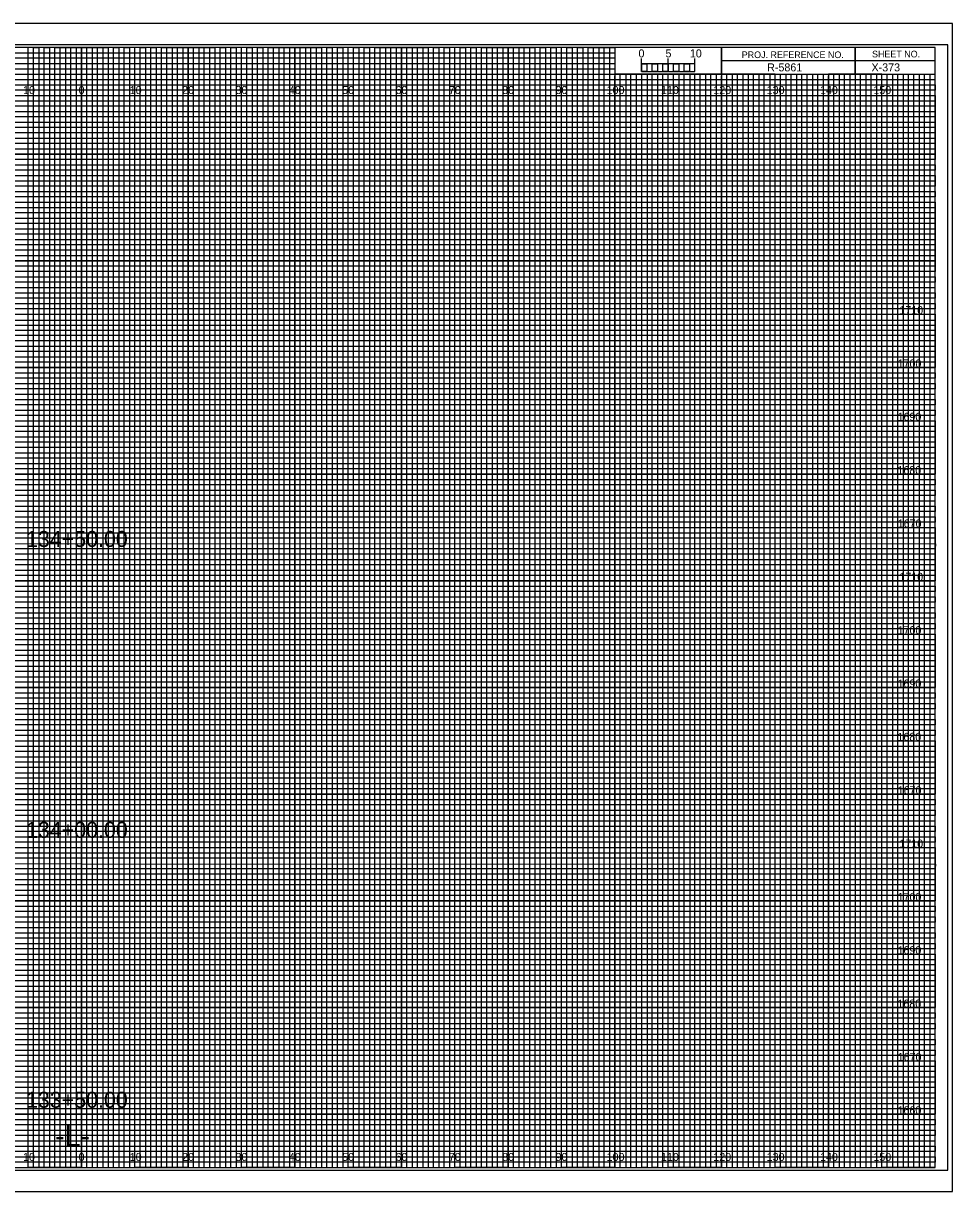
# Model space of a CAD drawing. Extents: x -13 to 323, y -5 to 2414.
# Drawn here: x 149.1 to 323.3, y 1975.5 to 2194.5 of the extents above; entities that cross this region are included whole.
import ezdxf

# ---------------------------------------------------------------- set-up
doc = ezdxf.new("R2010")
doc.units = 0
for name, color, linetype in [('Prop XS Alignment Label', 7, 'Continuous'), ('Prop XS Bar Scale Labels', 7, 'Continuous'), ('Prop XS Elevation Labels', 7, 'Continuous'), ('Prop XS Offset Labels', 7, 'Continuous'), ('Prop XS Project Number', 7, 'Continuous'), ('Prop XS Sheet Number', 7, 'Continuous'), ('Prop XS Station Labels', 7, 'Continuous'), ('Sheet Cross Section CELL', 7, 'Continuous'), ('Sheet Cross Section Grid Major CELL', 7, 'Continuous'), ('Sheet Cross Section Grid Middle CELL', 7, 'Continuous'), ('Sheet Cross Section Grid Minor 1 CELL', 7, 'Continuous'), ('Sheet Cross Section Grid Minor 2 CELL', 7, 'Continuous'), ('Sheet Cross Section Scale CELL', 7, 'Continuous'), ('Sheet Cutting Line CELL', 7, 'Continuous'), ('Sheet DOT Grid CELL', 7, 'Continuous'), ('Sheet Plot Border Inside CELL', 7, 'Continuous'), ('Sheet Plot Border Outside CELL', 7, 'Continuous')]:
    doc.layers.add(name, color=color, linetype=linetype)

msp = doc.modelspace()

# ---------------------------------------------------------------- linework, layer by layer
at = {"layer": 'Sheet Cross Section CELL'}
for p, q in [((305, 2190), (305, 2185)), ((305, 2185), (305, 2190)), ((280, 2187.5), (280, 2185)), ((320, 2187.49), (280, 2187.49)), ((280, 2185), (320, 2185))]:
    msp.add_line(p, q, dxfattribs=at)
for points in [[(320, 2190), (0, 2190), (0, 1980), (320, 1980)], [(280, 2190), (260, 2190), (260, 2185.03), (280, 2185.03)], [(320, 2190), (280, 2190), (280, 2185), (320, 2185)]]:
    msp.add_lwpolyline(points, close=True, dxfattribs=at)
at = {"layer": 'Sheet Cross Section Grid Major CELL'}
for p, q in [((150, 2190), (140, 2190)), ((150, 1980), (150, 2190)), ((170, 2190), (160, 2190)), ((160, 2190), (160, 1980)), ((170, 1980), (170, 2190)), ((190, 2190), (180, 2190)), ((180, 2190), (180, 1980)), ((190, 1980), (190, 2190)), ((210, 2190), (200, 2190)), ((200, 2190), (200, 1980)), ((210, 1980), (210, 2190)), ((230, 2190), (220, 2190)), ((220, 2190), (220, 1980)), ((230, 1980), (230, 2190)), ((250, 2190), (240, 2190)), ((240, 2190), (240, 1980)), ((250, 1980), (250, 2190)), ((260, 2190), (260, 1980)), ((270, 1980), (270, 2185)), ((290, 2185), (280, 2185)), ((280, 2185), (280, 1980)), ((290, 1980), (290, 2185)), ((310, 2185), (300, 2185)), ((300, 2185), (300, 1980)), ((310, 1980), (310, 2185)), ((160, 1980), (150, 1980)), ((180, 1980), (170, 1980)), ((200, 1980), (190, 1980)), ((220, 1980), (210, 1980)), ((240, 1980), (230, 1980)), ((260, 1980), (250, 1980)), ((280, 1980), (270, 1980)), ((300, 1980), (290, 1980)), ((320, 1980), (310, 1980)), ((320, 1980), (320, 1980))]:
    msp.add_line(p, q, dxfattribs=at)
for points in [[(0, 2180), (320, 2180), (320, 2170), (0, 2170)], [(0, 2160), (320, 2160), (320, 2150), (0, 2150)], [(0, 2140), (320, 2140), (320, 2130), (0, 2130)], [(0, 2120), (320, 2120), (320, 2110), (0, 2110)], [(0, 2100), (320, 2100), (320, 2090), (0, 2090)], [(0, 2080), (320, 2080), (320, 2070), (0, 2070)], [(0, 2060), (320, 2060), (320, 2050), (0, 2050)], [(0, 2040), (320, 2040), (320, 2030), (0, 2030)], [(0, 2020), (320, 2020), (320, 2010), (0, 2010)], [(0, 2000), (320, 2000), (320, 1990), (0, 1990)]]:
    msp.add_lwpolyline(points, dxfattribs=at)
at = {"layer": 'Sheet Cross Section Grid Middle CELL'}
for points in [[(145, 1980), (155, 1980), (155, 2190), (165, 2190), (165, 1980), (175, 1980), (175, 2190), (185, 2190), (185, 1980), (195, 1980), (195, 2190), (205, 2190), (205, 1980), (215, 1980), (215, 2190), (225, 2190), (225, 1980), (235, 1980), (235, 2190), (245, 2190), (245, 1980), (255, 1980), (255, 2190), (259.93, 2190), (260, 2190), (260, 2185), (264.99, 2185), (264.99, 1980), (275, 1980), (275, 2185), (285, 2185), (285, 1980), (295, 1980), (295, 2185), (305, 2185), (305, 1980), (315, 1980), (315, 2185)], [(0, 2185), (275, 2185)], [(0, 2165), (320, 2165), (320, 2175), (0, 2175)], [(0, 2145), (320, 2145), (320, 2155), (0, 2155)], [(0, 2125), (320, 2125), (320, 2135), (0, 2135)], [(0, 2105), (320, 2105), (320, 2115), (0, 2115)], [(0, 2085), (320, 2085), (320, 2095), (0, 2095)], [(0, 2065), (320, 2065), (320, 2075), (0, 2075)], [(0, 2045), (320, 2045), (320, 2055), (0, 2055)], [(0, 2025), (320, 2025), (320, 2035), (0, 2035)], [(0, 2005), (320, 2005), (320, 2015), (0, 2015)], [(0, 1985), (320, 1985), (320, 1995), (0, 1995)]]:
    msp.add_lwpolyline(points, dxfattribs=at)
at = {"layer": 'Sheet Cross Section Grid Minor 1 CELL'}
for p, q in [((0, 2189), (260, 2189)), ((260, 2187.98), (0, 2187.98)), ((260, 2189), (260, 2187.98)), ((0, 2187), (260, 2187)), ((260, 2185.89), (0, 2185.89)), ((260, 2187), (260, 2185.89)), ((0, 2184), (320, 2184))]:
    msp.add_line(p, q, dxfattribs=at)
for points in [[(0, 2183), (270, 2183), (320, 2183), (320, 2182), (0, 2182)], [(0, 2181), (320, 2181), (320, 2179), (0, 2179)], [(0, 2178), (320, 2178), (320, 2177), (0, 2176.98)], [(0, 2176), (320, 2176), (320, 2174), (0, 2174)], [(0, 2173), (320, 2173), (320, 2172), (0, 2172)], [(0, 2171), (320, 2171), (320, 2169), (0, 2169)], [(0, 2168), (320, 2168), (320, 2167), (0, 2167)], [(0, 2166), (320, 2166), (320, 2164), (0, 2164)], [(0, 2163), (320, 2163), (320, 2162), (0, 2162)], [(0, 2161), (320, 2161), (320, 2159), (0, 2159)], [(0, 2158), (320, 2158), (320, 2157), (0, 2157)], [(0, 2156), (320, 2156), (320, 2153.95), (320, 2153), (320, 2152), (0, 2152)], [(0, 2154), (320, 2154), (320, 2153), (0, 2153)], [(0, 2151), (320, 2151), (320, 2149), (0, 2149.03)], [(0, 2149.03), (320, 2149), (320, 2148), (0, 2148)], [(0, 2147), (320, 2147), (320, 2146), (0, 2146)], [(0, 2144), (320, 2144), (320, 2143), (0, 2143)], [(0, 2142), (320, 2142), (320, 2141), (0, 2141)], [(-0.07, 2138.89), (320, 2138.89), (320, 2137.88), (-0.07, 2137.88)], [(0, 2137), (320, 2137), (320, 2136), (0, 2136)], [(0, 2134), (320, 2134), (320, 2133), (0, 2133)], [(0, 2132), (320, 2132), (320, 2131), (0, 2131)], [(0, 2129), (320, 2129), (320, 2128), (0, 2128)], [(0, 2127), (320, 2127), (320, 2126), (0, 2126)], [(0, 2124), (320, 2124), (320, 2123), (0, 2123)], [(0, 2122), (320, 2122), (320, 2121), (0, 2121)], [(0, 2119), (320, 2119), (319.99, 2117.98), (0, 2118)], [(0, 2117), (320, 2117), (320, 2116), (0, 2116)], [(0, 2114), (320, 2114), (320, 2113), (0, 2113)], [(0, 2112), (320, 2112), (320, 2111), (0, 2111)], [(0, 2109), (320, 2109), (320, 2108), (0, 2108)], [(0, 2107), (320, 2107), (320, 2106), (0, 2106)], [(0, 2104), (320, 2104), (320, 2103), (0, 2103)], [(0, 2102), (320, 2102), (320, 2101), (0, 2101)], [(0, 2099), (320, 2099), (320, 2098), (0, 2098)], [(0, 2096.99), (320.07, 2096.91), (320, 2096), (0, 2096)], [(0, 2094), (320, 2094), (320, 2093), (0, 2093)], [(0, 2092), (320, 2092), (320, 2091), (0, 2091)], [(0, 2089), (320, 2089), (320, 2088), (0, 2088)], [(0, 2087), (320, 2087), (320, 2086), (0, 2086)], [(0, 2084), (320, 2084), (320, 2083), (0, 2083)], [(0, 2082), (320, 2082), (320, 2081), (0, 2081)], [(0, 2079), (320, 2079), (320, 2078), (0, 2078)], [(0, 2077), (320, 2077), (320, 2076), (0, 2076)], [(0, 2074), (320, 2074), (320, 2073), (0, 2073)], [(0, 2072), (320, 2072), (320, 2071), (0, 2071)], [(0, 2069), (320, 2069), (320, 2068), (0, 2068)], [(0, 2067), (320, 2067), (320, 2066), (0, 2066)], [(0, 2064), (320, 2064), (320, 2063), (0, 2063)], [(0, 2062), (320, 2062), (320, 2061), (0, 2061)], [(0, 2059), (320, 2059), (319.99, 2057.98), (0, 2058)], [(0, 2057), (320, 2057), (320, 2056), (0, 2056)], [(0, 2054), (320, 2054), (320, 2053), (0, 2053)], [(0, 2052), (320, 2052), (320, 2051), (0, 2051)], [(0, 2049), (320, 2049), (320, 2048), (0, 2048)], [(0, 2047), (320, 2047), (320, 2046), (0, 2046)], [(0, 2044), (320, 2044), (320, 2043), (0, 2043)], [(0, 2042), (320, 2042), (320, 2041), (0, 2041)], [(0, 2039), (320, 2039), (320, 2038), (0, 2038)], [(0, 2036.99), (320.07, 2036.91), (320, 2036), (0, 2036)], [(0, 2034), (320, 2034), (320, 2033), (0, 2033)], [(0, 2032), (320, 2032), (320, 2031), (0, 2031)], [(0, 2029), (320, 2029), (320, 2028), (0, 2028)], [(0, 2027), (320, 2027), (320, 2026), (0, 2026)], [(0, 2024), (320, 2024), (320, 2023), (0, 2023)], [(0, 2022), (320, 2022), (320, 2021), (0, 2021)], [(0, 2019), (320, 2019), (320, 2018), (0, 2018)], [(0, 2017), (320, 2017), (320, 2016), (0, 2016)], [(0, 2014), (320, 2014), (320, 2013), (0, 2013)], [(0, 2012), (320, 2012), (320, 2011), (0, 2011)], [(0, 2009), (320, 2009), (320, 2008), (0, 2008)], [(0, 2007), (320, 2007), (320, 2006), (0, 2006)], [(0, 2004), (320, 2004), (320, 2003), (0, 2003)], [(0, 2002), (320, 2002), (320, 2001), (0, 2001)], [(0, 1999), (320, 1999), (320, 1998), (0, 1998)], [(0, 1997), (320, 1997), (320, 1996), (0, 1996)], [(0, 1994), (320, 1994), (320, 1993), (0, 1993)], [(0, 1992), (320, 1992), (320, 1991), (0, 1991)], [(0, 1989), (320, 1989), (320, 1988), (0, 1988)], [(0, 1987), (320, 1987), (320, 1986), (0, 1986)], [(0, 1984), (320, 1984), (320, 1983), (0, 1983)], [(0, 1982), (320, 1982), (320, 1981), (0, 1981)]]:
    msp.add_lwpolyline(points, dxfattribs=at)
at = {"layer": 'Sheet Cross Section Grid Minor 2 CELL'}
for p, q in [((267, 2185), (266.01, 2185)), ((266.01, 2185), (266.01, 1980)), ((267, 1980), (267, 2185)), ((269, 2185), (268, 2185)), ((268, 2185), (268, 1980)), ((269, 1980), (269, 2185)), ((266.01, 1980), (265, 1980)), ((268, 1980), (267, 1980))]:
    msp.add_line(p, q, dxfattribs=at)
for points in [[(150, 1980), (151, 1980), (151, 2190), (152, 2190), (152, 1980)], [(152, 1980), (153, 1980), (153, 2190), (154, 2190), (154, 1980)], [(155, 1980), (156, 1980), (156, 2190), (157, 2190), (157, 1980)], [(157, 1980), (158, 1980), (158, 2190), (159, 2190), (159, 1980)], [(160, 1980), (161, 1980), (161, 2190), (162, 2190), (162, 1980)], [(162, 1980), (163, 1980), (163, 2190), (164, 2190), (164, 1980)], [(165, 1980), (166, 1980), (166, 2190), (167, 2190), (167, 1980)], [(167, 1980), (168, 1980), (168, 2190), (169, 2190), (169, 1980)], [(170, 1980), (171, 1980), (171, 2190), (172, 2190), (172, 1980)], [(172, 1980), (173, 1980), (173, 2190), (174, 2190), (174, 1980)], [(175, 1980), (176, 1980), (176, 2190), (177, 2190), (177, 1980)], [(177, 1980), (178, 1980), (178, 2190), (179, 2190), (179, 1980)], [(180, 1980), (181, 1980), (181, 2190), (182, 2190), (182, 1980)], [(182, 1980), (183, 1980), (183, 2190), (184, 2190), (184, 1980)], [(185, 1980), (186, 1980), (186, 2190), (187, 2190), (187, 1980)], [(187, 1980), (188, 1980), (188, 2190), (189, 2190), (189, 1980)], [(190, 1980), (191, 1980), (191, 2190), (192, 2190), (192, 1980)], [(192, 1980), (193, 1980), (193, 2190), (194, 2190), (194, 1980)], [(195, 1980), (196, 1980), (196, 2190), (197, 2190), (197, 1980)], [(197, 1980), (198, 1980), (198, 2190), (199, 2190), (199, 1980)], [(200, 1980), (201, 1980), (201, 2190), (202, 2190), (202, 1980)], [(202, 1980), (203, 1980), (203, 2190), (204, 2190), (204, 1980)], [(205, 1980), (206, 1980), (206, 2190), (207, 2190), (207, 1980)], [(207, 1980), (208, 1980), (208, 2190), (209, 2190), (209, 1980)], [(210, 1980), (211, 1980), (211, 2190), (212, 2190), (212, 1980)], [(212, 1980), (213, 1980), (213, 2190), (214, 2190), (214, 1980)], [(215, 1980), (216, 1980), (216, 2190), (217, 2190), (217, 1980)], [(217, 1980), (218, 1980), (218, 2190), (219, 2190), (219, 1980)], [(220, 1980), (221, 1980), (221, 2190), (222, 2190), (222, 1980)], [(222, 1980), (223, 1980), (223, 2190), (224, 2190), (224, 1980)], [(225, 1980), (226, 1980), (226, 2190), (227, 2190), (227, 1980)], [(227, 1980), (228, 1980), (228, 2190), (229, 2190), (229, 1980)], [(230, 1980), (231, 1980), (231, 2190), (232, 2190), (232, 1980)], [(232, 1980), (233, 1980), (233, 2190), (234, 2190), (234, 1980)], [(235, 1980), (236, 1980), (236, 2190), (237, 2190), (237, 1980)], [(237, 1980), (238, 1980), (238, 2190), (239, 2190), (239, 1980)], [(240, 1980), (241, 1980), (241, 2190), (242, 2190), (242, 1980)], [(242, 1980), (243, 1980), (243, 2190), (244, 2190), (244, 1980)], [(245, 1980), (246, 1980), (246, 2190), (247, 2190), (247, 1980)], [(247, 1980), (248, 1980), (248, 2190), (249, 2190), (249, 1980)], [(250, 1980), (251, 1980), (251, 2190), (252, 2190), (252, 1980)], [(252, 1980), (253, 1980), (253, 2190), (254, 2190), (254, 1980)], [(255, 1980), (256, 1980), (256, 2190), (257, 2190), (257, 1980)], [(257, 1980), (258, 1980), (258, 2190), (259, 2190), (259, 1980)], [(260, 1980), (261, 1980), (261, 2185), (262.02, 2185), (262.02, 1980)], [(262, 1980), (263, 1980), (263, 2185), (263.99, 2185), (263.99, 1980)], [(270, 1980), (270.98, 1980), (270.98, 2185), (272, 2185), (272, 1980)], [(272, 1980), (273, 1980), (273, 2185), (274.05, 2185), (274.05, 1980)], [(275, 1980), (276, 1980), (276, 2185), (277, 2185), (277, 1980)], [(277, 1980), (278, 1980), (278, 2185), (279, 2185), (279, 1980)], [(280, 1980), (281, 1980), (281, 2185), (282, 2185), (282, 1980)], [(282, 1980), (283, 1980), (283, 2185), (284, 2185), (284, 1980)], [(285, 1980), (286, 1980), (286, 2185), (287, 2185), (287, 1980)], [(287, 1980), (288, 1980), (288, 2185), (289, 2185), (289, 1980)], [(290, 1980), (291, 1980), (291, 2185), (292, 2185), (292, 1980)], [(292, 1980), (293, 1980), (293, 2185), (294, 2185), (294, 1980)], [(295, 1980), (296, 1980), (296, 2185), (297, 2185), (297, 1980)], [(297, 1980), (298, 1980), (298, 2185), (299, 2185), (299, 1980)], [(300, 1980), (301, 1980), (301, 2185), (302, 2185), (302, 1980)], [(302, 1980), (303, 1980), (303, 2185), (304, 2185), (304, 1980)], [(305, 1980), (306, 1980), (306, 2185), (307, 2185), (307, 1980)], [(307, 1980), (308, 1980), (308, 2185), (309, 2185), (309, 1980)], [(310, 1980), (311, 1980), (311, 2185), (312, 2185), (312, 1980)], [(312, 1980), (313, 1980), (313, 2185), (314, 2185), (314, 1980)], [(315, 1980), (316, 1980), (316, 2185), (317, 2185), (317, 1980)], [(317, 1980), (318, 1980), (318, 2185), (319, 2185), (319, 1980)]]:
    msp.add_lwpolyline(points, dxfattribs=at)
at = {"layer": 'Sheet Cross Section Scale CELL'}
for p, q in [((265, 2185.49), (265, 2187.9)), ((265, 2186.9), (265, 2187.9)), ((270, 2185.49), (270, 2187.9)), ((275, 2185.49), (275, 2187.9)), ((275, 2186.9), (275, 2187.9))]:
    msp.add_line(p, q, dxfattribs=at)
for points in [[(275, 2186.9), (265, 2186.9), (265, 2185.49), (275, 2185.49)], [(265, 2186.9), (266, 2186.9), (266, 2185.49), (265, 2185.49)], [(267, 2186.9), (268, 2186.9), (268, 2185.49), (267, 2185.49)], [(269, 2186.9), (270, 2186.9), (270, 2185.49), (269, 2185.49)], [(271, 2186.9), (272, 2186.9), (272, 2185.49), (271, 2185.49)], [(273, 2186.9), (274, 2186.9), (274, 2185.49), (273, 2185.49)]]:
    msp.add_lwpolyline(points, close=True, dxfattribs=at)
at = {"layer": 'Sheet Cutting Line CELL'}
for p, q in [((323.3, 2194.5), (-13.4, 2194.5)), ((-13.4, 1975.5), (323.3, 1975.5))]:
    msp.add_line(p, q, dxfattribs=at)
at = {"layer": 'Sheet DOT Grid CELL'}
for p, q in [((150, 1980), (150, 2190)), ((160, 1980), (160, 2190)), ((170, 1980), (170, 2190)), ((180, 1980), (180, 2190)), ((190, 1980), (190, 2190)), ((200, 1980), (200, 2190)), ((210, 1980), (210, 2190)), ((220, 1980), (220, 2190)), ((230, 1980), (230, 2190)), ((240, 1980), (240, 2190)), ((250, 1980), (250, 2190)), ((260, 1980), (260, 2184.69)), ((270, 1980), (270, 2184.69)), ((280, 1980), (280, 2184.69)), ((290, 1980), (290, 2184.69)), ((300, 1980), (300, 2184.69)), ((310, 1980), (310, 2184.69)), ((0, 2180), (320, 2180)), ((0, 2170), (320, 2170)), ((0, 2160), (320, 2160)), ((0, 2150), (320, 2150)), ((0, 2140), (320, 2140)), ((0, 2130), (320, 2130)), ((0, 2120), (320, 2120)), ((0, 2110), (320, 2110)), ((0, 2100), (320, 2100)), ((0, 2090), (320, 2090)), ((0, 2080), (320, 2080)), ((0, 2070), (320, 2070)), ((0, 2060), (320, 2060)), ((0, 2050), (320, 2050)), ((0, 2040), (320, 2040)), ((0, 2030), (320, 2030)), ((0, 2020), (320, 2020)), ((0, 2010), (320, 2010)), ((0, 2000), (320, 2000)), ((0, 1990), (320, 1990))]:
    msp.add_line(p, q, dxfattribs=at)
at = {"layer": 'Sheet Plot Border Inside CELL'}
msp.add_lwpolyline([(-10.8, 1979.5), (322.4, 1979.5), (322.4, 2190.5), (-10.8, 2190.5)], close=True, dxfattribs=at)
at = {"layer": 'Sheet Plot Border Outside CELL'}
msp.add_lwpolyline([(-13.4, 1975.5), (323.3, 1975.5), (323.3, 2194.5), (-13.4, 2194.5)], close=True, dxfattribs=at)

# ---------------------------------------------------------------- texts
at = {"layer": 'Prop XS Alignment Label'}
msp.add_text('-L-', height=4, dxfattribs=at).set_placement((155.06, 1984))
at = {"layer": 'Prop XS Bar Scale Labels'}
for s, p in [('5', (269.47, 2188.12)), ('10', (274.04, 2188.12))]:
    msp.add_text(s, height=1.5, dxfattribs=at).set_placement(p)
at = {"layer": 'Prop XS Elevation Labels'}
for s, p in [('1710', (313.31, 2140)), ('1700', (312.98, 2130)), ('1690', (312.97, 2120)), ('1680', (312.95, 2110)), ('1670', (313, 2100)), ('1710', (313.31, 2090)), ('1700', (312.98, 2080)), ('1690', (312.97, 2070)), ('1680', (312.95, 2060)), ('1670', (313, 2050)), ('1710', (313.31, 2040)), ('1700', (312.98, 2030)), ('1690', (312.97, 2020)), ('1680', (312.95, 2010)), ('1670', (313, 2000)), ('1660', (312.97, 1990))]:
    msp.add_text(s, height=1.5, dxfattribs=at).set_placement(p)
at = {"layer": 'Prop XS Offset Labels'}
for s, p in [('10', (149.04, 2181.25)), ('0', (159.45, 2181.25)), ('0', (159.45, 2181.25)), ('10', (169.04, 2181.25)), ('20', (178.86, 2181.25)), ('30', (188.86, 2181.25)), ('40', (198.86, 2181.25)), ('50', (208.86, 2181.25)), ('60', (218.86, 2181.25)), ('70', (228.86, 2181.25)), ('80', (238.86, 2181.25)), ('90', (248.86, 2181.25)), ('100', (258.44, 2181.25)), ('110', (268.62, 2181.25)), ('120', (278.44, 2181.25)), ('130', (288.44, 2181.25)), ('140', (298.44, 2181.25)), ('150', (308.44, 2181.25)), ('10', (149.04, 1981.25)), ('0', (159.45, 1981.25)), ('0', (159.45, 1981.25)), ('10', (169.04, 1981.25)), ('20', (178.86, 1981.25)), ('30', (188.86, 1981.25)), ('40', (198.86, 1981.25)), ('50', (208.86, 1981.25)), ('60', (218.86, 1981.25)), ('70', (228.86, 1981.25)), ('80', (238.86, 1981.25)), ('90', (248.86, 1981.25)), ('100', (258.44, 1981.25)), ('110', (268.62, 1981.25)), ('120', (278.44, 1981.25)), ('130', (288.44, 1981.25)), ('140', (298.44, 1981.25)), ('150', (308.44, 1981.25))]:
    msp.add_text(s, height=1.5, dxfattribs=at).set_placement(p)
at = {"layer": 'Prop XS Project Number'}
msp.add_text('R-5861', height=1.5, dxfattribs=at).set_placement((288.53, 2185.5))
at = {"layer": 'Prop XS Sheet Number'}
msp.add_text('X-373', height=1.5, dxfattribs=at).set_placement((308.09, 2185.5))
at = {"layer": 'Prop XS Station Labels'}
for s, p in [('134+50.00', (149.59, 2096.35)), ('134+00.00', (149.59, 2041.82)), ('133+50.00', (149.59, 1991.22))]:
    msp.add_text(s, height=3, dxfattribs=at).set_placement(p)
at = {"layer": 'Sheet Cross Section CELL'}
for s, p in [('PROJ. REFERENCE NO.', (283.77, 2187.99)), ('SHEET NO.', (308.19, 2188.12))]:
    msp.add_text(s, height=1.25, dxfattribs=at).set_placement(p)
at = {"layer": 'Sheet Cross Section Scale CELL'}
msp.add_text('0', height=1.5, dxfattribs=at).set_placement((264.41, 2188.12))

doc.saveas('drawing.dxf')
